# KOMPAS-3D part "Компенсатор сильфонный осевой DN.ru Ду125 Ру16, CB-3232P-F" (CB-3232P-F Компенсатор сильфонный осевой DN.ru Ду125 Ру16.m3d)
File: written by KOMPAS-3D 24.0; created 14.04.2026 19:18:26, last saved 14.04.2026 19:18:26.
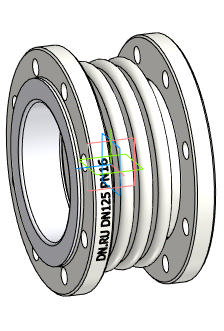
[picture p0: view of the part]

Document properties: Автор: DN.RU; Полное имя файла: D:\PROJECT CAD\DN.RU\..199(ACTUALE). CB-3232P-F Компенсатор сильфонный осевой DN.ru\Исходники\DN125\CB-3232P-F Компенсатор сильфонный осевой DN.ru Ду125 Ру16.m3d

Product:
- Body: Твердое тело1  | qty 1
    Масса: 14.285243
- Part/product: Компенсатор сильфонный осевой DN.ru Ду125 Ру16  | designation CB-3232P-F
    Масса: 11.2
    Раздел спецификации: Прочие изделия
    Комментарий: D140-02142
    Примечание: D140-02142
    additional columns: Типовые

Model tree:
1. Твердое тело1  (labels: Твердое тело1)

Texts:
  CB-3232P-F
